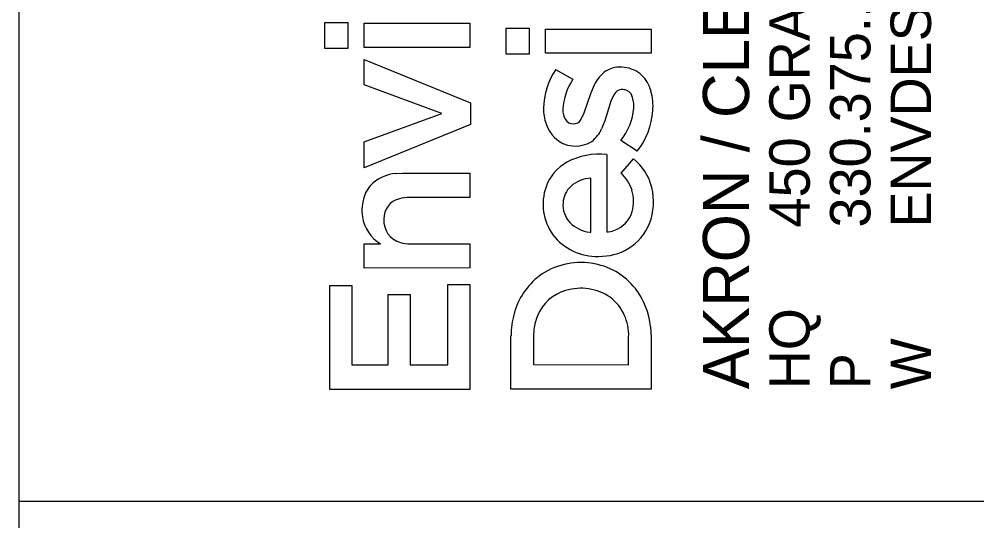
# Model space of a CAD drawing. Extents: x -4.4 to 34, y 0 to 22.
# Drawn here: x 32 to 33.181, y 2.476 to 3.094 of the extents above; entities that cross this region are included whole.
import ezdxf

# ---------------------------------------------------------------- set-up
doc = ezdxf.new("R2010")
doc.units = 0
doc.layers.add('PF_X_Ground_Line', color=7, linetype='Continuous')
doc.layers.add('UT_X_FO', color=7, linetype='Continuous')

msp = doc.modelspace()

# ---------------------------------------------------------------- linework, layer by layer
at = {"layer": 'PF_X_Ground_Line'}
for p, q in [((32.3771, 3.0582), (32.3771, 3.0903)), ((32.3771, 3.0903), (32.4054, 3.0903)), ((32.4054, 3.0903), (32.4054, 3.0582)), ((32.4254, 3.0594), (32.4254, 3.0893)), ((32.4254, 3.0893), (32.5557, 3.0893)), ((32.5557, 3.0893), (32.5557, 3.0594)), ((32.6005, 3.0511), (32.6005, 3.0832)), ((32.6005, 3.0832), (32.6289, 3.0832)), ((32.6289, 3.0832), (32.6289, 3.0511)), ((32.6489, 3.0523), (32.6489, 3.0822)), ((32.6489, 3.0822), (32.7792, 3.0822)), ((32.7792, 3.0822), (32.7792, 3.0523)), ((32.5557, 3.0594), (32.4254, 3.0594)), ((32.4054, 3.0582), (32.3771, 3.0582)), ((32.6289, 3.0511), (32.6005, 3.0511)), ((32.7792, 3.0523), (32.6489, 3.0523)), ((32.4254, 3.0133), (32.4254, 3.0446)), ((32.4254, 3.0446), (32.5567, 2.9913)), ((32.6615, 3.0321), (32.6827, 3.0203)), ((32.5212, 2.978), (32.4254, 3.0133)), ((32.7048, 3.0026), (32.7104, 3.0153)), ((32.6967, 2.9787), (32.7048, 3.0026)), ((32.7334, 3.001), (32.7298, 2.9933)), ((32.5567, 2.9913), (32.5567, 2.9644)), ((32.7298, 2.9933), (32.7221, 2.9688)), ((32.4254, 2.9429), (32.5212, 2.978)), ((32.693, 2.9712), (32.6967, 2.9787)), ((32.5567, 2.9644), (32.4254, 2.9109)), ((32.7221, 2.9688), (32.7182, 2.9592)), ((32.4254, 2.9109), (32.4254, 2.9429)), ((32.7621, 2.9314), (32.742, 2.9447)), ((32.7245, 2.9275), (32.7246, 2.8319)), ((32.7423, 2.9046), (32.7577, 2.922)), ((32.4644, 2.904), (32.4729, 2.9044)), ((32.4729, 2.9044), (32.5557, 2.9044)), ((32.5557, 2.9044), (32.5557, 2.8746)), ((32.7049, 2.8318), (32.7049, 2.8983)), ((32.5557, 2.8746), (32.4814, 2.8746)), ((32.7036, 2.8317), (32.7049, 2.8318)), ((32.4254, 2.7875), (32.4254, 2.8173)), ((32.4254, 2.8173), (32.4455, 2.8173)), ((32.4822, 2.8173), (32.5557, 2.8173)), ((32.5557, 2.8173), (32.5557, 2.7876)), ((32.5557, 2.7876), (32.4254, 2.7875)), ((32.383, 2.6379), (32.383, 2.766)), ((32.383, 2.766), (32.4101, 2.766)), ((32.4101, 2.766), (32.4101, 2.6683)), ((32.5286, 2.6683), (32.5286, 2.7672)), ((32.5286, 2.7672), (32.5557, 2.7672)), ((32.5557, 2.7672), (32.5557, 2.6379)), ((32.455, 2.6683), (32.455, 2.7549)), ((32.455, 2.7549), (32.4822, 2.7549)), ((32.4822, 2.7549), (32.4822, 2.6683)), ((32.6347, 2.7118), (32.6341, 2.7023)), ((32.7785, 2.715), (32.7792, 2.7021)), ((32.6064, 2.638), (32.6064, 2.704)), ((32.6341, 2.7023), (32.6341, 2.6684)), ((32.7515, 2.6683), (32.7515, 2.7024)), ((32.7792, 2.7021), (32.7792, 2.638)), ((32.4101, 2.6683), (32.455, 2.6683)), ((32.4822, 2.6683), (32.5286, 2.6683)), ((32.6341, 2.6684), (32.7515, 2.6683)), ((32.5557, 2.6379), (32.383, 2.6379)), ((32.7792, 2.638), (32.6064, 2.638))]:
    msp.add_line(p, q, dxfattribs=at)
for points in [[(32.3771, 3.0582), (32.3771, 3.0903), (32.4054, 3.0903), (32.4054, 3.0582)], [(32.4254, 3.0594), (32.4254, 3.0893), (32.5557, 3.0893), (32.5557, 3.0594)], [(32.6005, 3.0511), (32.6005, 3.0832), (32.6289, 3.0832), (32.6289, 3.0511)], [(32.6489, 3.0523), (32.6489, 3.0822), (32.7792, 3.0822), (32.7792, 3.0523)], [(32.4254, 2.9109), (32.4254, 2.9429), (32.5212, 2.978), (32.4254, 3.0133), (32.4254, 3.0446), (32.5567, 2.9913), (32.5567, 2.9644)], [(32.383, 2.6379), (32.383, 2.766), (32.4101, 2.766), (32.4101, 2.6683), (32.455, 2.6683), (32.455, 2.7549), (32.4822, 2.7549), (32.4822, 2.6683), (32.5286, 2.6683), (32.5286, 2.7672), (32.5557, 2.7672), (32.5557, 2.6379)]]:
    msp.add_lwpolyline(points, close=True, dxfattribs=at)
for points in [[(32.6615, 3.0321), (32.6827, 3.0203)], [(32.693, 2.9712), (32.6967, 2.9787), (32.7048, 3.0026), (32.7104, 3.0153)], [(32.7334, 3.001), (32.7298, 2.9933), (32.7221, 2.9688), (32.7182, 2.9592)], [(32.7621, 2.9314), (32.742, 2.9447)], [(32.7245, 2.9275), (32.7246, 2.8319)], [(32.7423, 2.9046), (32.7577, 2.922)], [(32.4644, 2.904), (32.4729, 2.9044), (32.5557, 2.9044), (32.5557, 2.8746), (32.4814, 2.8746)], [(32.7036, 2.8317), (32.7049, 2.8318), (32.7049, 2.8983)], [(32.4254, 2.7875), (32.4254, 2.8173), (32.4455, 2.8173)], [(32.4822, 2.8173), (32.5557, 2.8173), (32.5557, 2.7876), (32.4254, 2.7875)], [(32.7785, 2.715), (32.7792, 2.7021), (32.7792, 2.638), (32.6064, 2.638)], [(32.6347, 2.7118), (32.6341, 2.7023), (32.6341, 2.6684), (32.7515, 2.6683), (32.7515, 2.7024)], [(32.6064, 2.638), (32.6064, 2.704)]]:
    msp.add_lwpolyline(points, dxfattribs=at)
for centre, radius, start, end in [((32.7406, 3.0026), 0.0326, 80.1719, 122.5197), ((32.7406, 3.0026), 0.0326, 80.1719, 122.5197), ((32.7364, 2.9826), 0.0897, 146.531, 178.7571), ((32.7364, 2.9826), 0.0897, 146.531, 178.7571), ((32.7466, 2.9971), 0.0405, 125.5118, 153.4159), ((32.7466, 2.9971), 0.0405, 125.5118, 153.4159), ((32.7428, 2.9982), 0.0367, 47.7934, 84.6892), ((32.7428, 2.9982), 0.0367, 47.7934, 84.6892), ((32.7379, 2.9946), 0.0427, 14.9966, 46.2063), ((32.7379, 2.9946), 0.0427, 14.9966, 46.2063), ((32.7452, 2.9789), 0.0749, 146.5112, 176.9101), ((32.7452, 2.9789), 0.0749, 146.5112, 176.9101), ((32.7438, 2.9963), 0.0114, 76.6609, 155.7053), ((32.7438, 2.9963), 0.0114, 76.6609, 155.7053), ((32.744, 2.9951), 0.0126, 21.5098, 78.5262), ((32.744, 2.9951), 0.0126, 21.5098, 78.5262), ((32.7259, 2.9877), 0.0321, 354.5726, 22.068), ((32.7259, 2.9877), 0.0321, 354.5726, 22.068), ((32.7104, 2.9867), 0.0712, 355.8306, 15.3914), ((32.7104, 2.9867), 0.0712, 355.8306, 15.3914), ((32.6967, 2.9824), 0.0501, 177.5366, 222.7932), ((32.6967, 2.9824), 0.0501, 177.5366, 222.7932), ((32.6931, 2.9823), 0.0228, 178.4747, 211.0868), ((32.6931, 2.9823), 0.0228, 178.4747, 211.0868), ((32.6825, 2.9915), 0.0757, 321.811, 354.7969), ((32.6825, 2.9915), 0.0757, 321.811, 354.7969), ((32.6895, 2.9882), 0.0922, 321.9777, 355.8738), ((32.6895, 2.9882), 0.0922, 321.9777, 355.8738), ((32.6833, 2.9767), 0.0115, 212.2368, 268.3777), ((32.6833, 2.9767), 0.0115, 212.2368, 268.3777), ((32.6834, 2.9759), 0.0107, 267.716, 333.7337), ((32.6834, 2.9759), 0.0107, 267.716, 333.7337), ((32.681, 2.9758), 0.0408, 308.0877, 335.9874), ((32.681, 2.9758), 0.0408, 308.0877, 335.9874), ((32.686, 2.9753), 0.0375, 225.9854, 302.4797), ((32.686, 2.9753), 0.0375, 225.9854, 302.4797), ((32.7024, 2.8691), 0.0558, 118.8308, 160.6244), ((32.7024, 2.8691), 0.0558, 118.8308, 160.6244), ((32.7152, 2.8441), 0.0838, 83.615, 118.2876), ((32.7152, 2.8441), 0.0838, 83.615, 118.2876), ((32.7174, 2.8717), 0.0644, 13.5336, 51.3615), ((32.7174, 2.8717), 0.0644, 13.5336, 51.3615), ((32.4687, 2.8543), 0.0499, 94.9696, 130.2225), ((32.4687, 2.8543), 0.0499, 94.9696, 130.2225), ((32.7079, 2.8561), 0.0424, 94.008, 130.8817), ((32.7079, 2.8561), 0.0424, 94.008, 130.8817), ((32.7038, 2.8656), 0.0549, 19.0357, 45.4406), ((32.7038, 2.8656), 0.0549, 19.0357, 45.4406), ((32.4635, 2.8626), 0.0402, 132.2219, 161.6818), ((32.4635, 2.8626), 0.0402, 132.2219, 161.6818), ((32.7104, 2.8661), 0.0644, 160.5201, 215.7831), ((32.7104, 2.8661), 0.0644, 160.5201, 215.7831), ((32.7005, 2.8663), 0.0298, 132.9851, 177.179), ((32.7005, 2.8663), 0.0298, 132.9851, 177.179), ((32.7107, 2.8697), 0.047, 344.6059, 17.007), ((32.7107, 2.8697), 0.047, 344.6059, 17.007), ((32.7064, 2.8692), 0.0758, 339.3542, 13.3785), ((32.7064, 2.8692), 0.0758, 339.3542, 13.3785), ((32.4787, 2.8582), 0.056, 162.2736, 187.7919), ((32.4787, 2.8582), 0.056, 162.2736, 187.7919), ((32.4748, 2.8487), 0.025, 103.6865, 182.2187), ((32.4748, 2.8487), 0.025, 103.6865, 182.2187), ((32.4811, 2.8286), 0.046, 89.6049, 105.3284), ((32.4811, 2.8286), 0.046, 89.6049, 105.3284), ((32.7017, 2.865), 0.0311, 175.0013, 223.283), ((32.7017, 2.865), 0.0311, 175.0013, 223.283), ((32.4703, 2.858), 0.0476, 188.962, 238.7037), ((32.4703, 2.858), 0.0476, 188.962, 238.7037), ((32.4773, 2.8456), 0.0276, 175.5854, 255.1439), ((32.4773, 2.8456), 0.0276, 175.5854, 255.1439), ((32.7224, 2.8671), 0.035, 288.0077, 343.5508), ((32.7224, 2.8671), 0.035, 288.0077, 343.5508), ((32.7089, 2.8736), 0.0423, 225.0619, 262.7974), ((32.7089, 2.8736), 0.0423, 225.0619, 262.7974), ((32.7189, 2.8652), 0.0626, 300.9427, 338.7323), ((32.7189, 2.8652), 0.0626, 300.9427, 338.7323), ((32.7125, 2.8705), 0.0687, 217.7452, 271.6543), ((32.7125, 2.8705), 0.0687, 217.7452, 271.6543), ((32.7247, 2.8522), 0.0202, 269.7003, 294.8711), ((32.7247, 2.8522), 0.0202, 269.7003, 294.8711), ((32.4818, 2.8595), 0.0422, 254.0916, 270.5284), ((32.4818, 2.8595), 0.0422, 254.0916, 270.5284), ((32.7155, 2.8724), 0.0706, 269.2048, 300.3341), ((32.7155, 2.8724), 0.0706, 269.2048, 300.3341), ((32.6923, 2.7079), 0.0864, 81.194, 125.9984), ((32.6923, 2.7079), 0.0864, 81.194, 125.9984), ((32.6946, 2.7113), 0.0827, 37.8521, 82.402), ((32.6946, 2.7113), 0.0827, 37.8521, 82.402), ((32.6939, 2.7089), 0.0865, 127.2362, 165.148), ((32.6939, 2.7089), 0.0865, 127.2362, 165.148), ((32.6889, 2.7078), 0.054, 106.1881, 157.3861), ((32.6889, 2.7078), 0.054, 106.1881, 157.3861), ((32.6928, 2.6986), 0.0639, 55.6727, 107.2093), ((32.6928, 2.6986), 0.0639, 55.6727, 107.2093), ((32.6859, 2.7057), 0.0931, 5.7333, 37.304), ((32.6859, 2.7057), 0.0931, 5.7333, 37.304), ((32.6929, 2.705), 0.0587, 357.4662, 52.2665), ((32.6929, 2.705), 0.0587, 357.4662, 52.2665), ((32.7143, 2.7028), 0.1078, 164.7861, 179.3704), ((32.7143, 2.7028), 0.1078, 164.7861, 179.3704), ((32.6983, 2.7039), 0.0641, 157.3571, 172.9275), ((32.6983, 2.7039), 0.0641, 157.3571, 172.9275)]:
    msp.add_arc(centre, radius, start, end, dxfattribs=at)
at = {"layer": 'UT_X_FO'}
for p, q in [((32, 0.5), (32, 21.5)), ((32, 2.5), (33.5, 2.5))]:
    msp.add_line(p, q, dxfattribs=at)

# ---------------------------------------------------------------- texts
at = {"layer": 'PF_X_Ground_Line'}
for s, height, p in [('450 GRANT ST., AKRON, OH  44311', 0.049846, (32.9749, 2.8374)), ('AKRON / CLEVELAND / COLUMBUS', 0.056969, (32.9001, 2.638)), ('ENVDESIGNGROUP.COM', 0.049846, (33.1244, 2.8374)), ('330.375.1390', 0.049846, (33.0497, 2.8374)), ('HQ ', 0.04985, (32.9749, 2.638)), ('W', 0.0498, (33.1244, 2.638)), ('P', 0.0498, (33.0497, 2.638))]:
    msp.add_text(s, height=height, rotation=90, dxfattribs=at).set_placement(p)

doc.saveas('drawing.dxf')
